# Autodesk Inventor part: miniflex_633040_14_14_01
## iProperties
Shininess: 64.0
Length Units: 11269
Angle Units: 11279
Time Units: 11290
Mass Units: 11283
Length Display Precision: 3
Angle Display Precision: 2
Compacted: True
Part Number: miniflex_633040_14_14_01
Document SubType Name: Modeling
Created: 2005-02
Material: Par défaut
Designer: LEGERET Philippe
Density: 0.0
Volumn: 0.0
Area: 0.0
PropertySet Name: Model Information
Control State: 0
Master: False
Checked Out: False
Author: LEGERET Philippe
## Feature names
1. Base1
